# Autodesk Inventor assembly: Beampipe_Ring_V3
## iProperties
Shininess: 64.0
Length Units: 11269
Angle Units: 11279
Time Units: 11290
Mass Units: 11283
Length Display Precision: 3
Angle Display Precision: 2
Compacted: True
Created: 2004-08
Part Number: Beampipe_Ring_V3
Document SubType Name: Assembly
Designer: John Blackburn
Manufacturer: Standard
Standards Organization: Custom
Density: 0.0
Volumn: 0.0
Area: 0.0
PropertySet Name: Model Information
Control State: 0
Master: False
Checked Out: False
Author: John Blackburn
